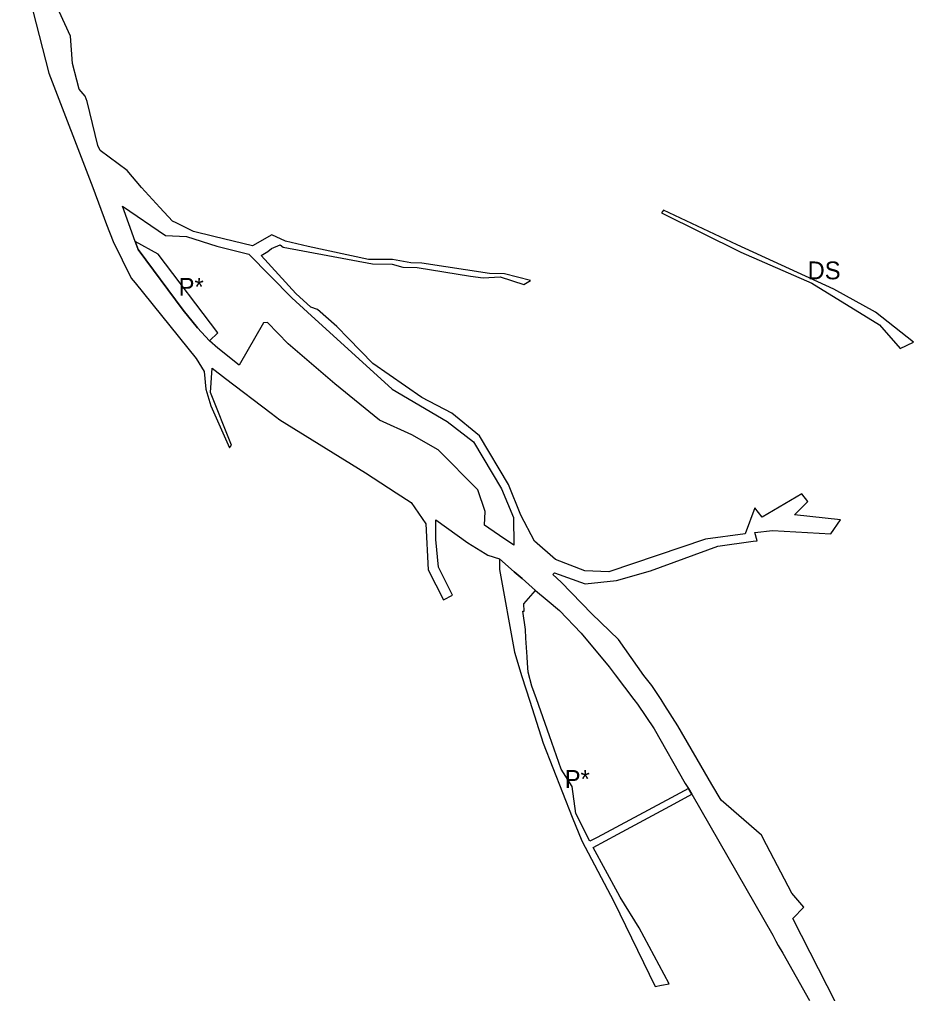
# Model space of a CAD drawing. Extents: x -477304 to -465641, y -1159113 to -1149285.
# Drawn here: x -474865.2 to -474412.9, y -1155046.4 to -1154553.8 of the extents above; entities that cross this region are included whole.
import ezdxf

# ---------------------------------------------------------------- set-up
doc = ezdxf.new("R2010")
doc.units = 0
doc.layers.add('34', color=7, linetype='Continuous')
doc.layers.add('35', color=7, linetype='Continuous')

msp = doc.modelspace()

# ---------------------------------------------------------------- linework, layer by layer
at = {"layer": '34'}
for p, q in [((-474806.65, -1154666.07), (-474805.24, -1154670.15)), ((-474795.11, -1154672.55), (-474806.65, -1154666.07)), ((-474805.24, -1154670.15), (-474782.43, -1154700.72)), ((-474764.82, -1154712.21), (-474795.11, -1154672.55)), ((-474769.12, -1154716.23), (-474764.82, -1154712.21)), ((-474614.91, -1154833.09), (-474622.36, -1154826.48)), ((-474622.36, -1154826.48), (-474622.33, -1154831.94)), ((-474610.93, -1154836.56), (-474614.91, -1154833.09)), ((-474604.08, -1154842.58), (-474610.93, -1154836.56)), ((-474610.12, -1154849.34), (-474604.08, -1154842.58)), ((-474609.89, -1154852.95), (-474610.12, -1154849.34)), ((-474609.01, -1154866.68), (-474609.29, -1154862.3)), ((-474608.41, -1154876.12), (-474609.01, -1154866.68)), ((-474608.21, -1154879.35), (-474608.41, -1154876.12)), ((-474603.72, -1154897.29), (-474605.96, -1154890.99)), ((-474607.04, -1154898.47), (-474600.23, -1154919.72)), ((-474597.09, -1154916.02), (-474603.72, -1154897.29)), ((-474526.67, -1154942.72), (-474535.48, -1154947.42)), ((-474525.04, -1154945.58), (-474526.67, -1154942.72)), ((-474535.48, -1154947.42), (-474572.91, -1154967.39)), ((-474533.92, -1154950.37), (-474525.04, -1154945.58)), ((-474562.54, -1154965.79), (-474533.92, -1154950.37)), ((-474574.98, -1154972.58), (-474562.54, -1154965.79)), ((-474562.48, -1154995.51), (-474574.98, -1154972.58)), ((-474536.56, -1155041.38), (-474551.7, -1155013.07)), ((-474540.39, -1155042.17), (-474536.56, -1155041.38)), ((-474543.58, -1155042.83), (-474540.39, -1155042.17))]:
    msp.add_line(p, q, dxfattribs=at)
for points in [[(-474782.43, -1154700.72), (-474775.12, -1154709.75), (-474769.12, -1154716.23)], [(-474622.33, -1154831.94), (-474614.8, -1154873.75), (-474611.04, -1154885.99), (-474607.04, -1154898.47)], [(-474609.29, -1154862.3), (-474610.56, -1154853.04), (-474609.89, -1154852.95)], [(-474605.96, -1154890.99), (-474607.92, -1154883.93), (-474608.21, -1154879.35)], [(-474585.68, -1154941.61), (-474591.13, -1154932.86), (-474597.09, -1154916.02)], [(-474600.23, -1154919.72), (-474585.53, -1154957.25), (-474580.79, -1154969.17), (-474564.55, -1154999.77), (-474543.58, -1155042.83)], [(-474572.91, -1154967.39), (-474576.61, -1154969.37), (-474583.78, -1154955.28), (-474585.68, -1154941.61)], [(-474551.7, -1155013.07), (-474561.35, -1154997.58), (-474562.48, -1154995.51)]]:
    msp.add_lwpolyline(points, dxfattribs=at)
at = {"layer": '35'}
for p, q in [((-474838.31, -1154576.14), (-474839.4, -1154562.29)), ((-474830.9, -1154595.31), (-474831.91, -1154592.5)), ((-474825.49, -1154617.48), (-474830.9, -1154595.31)), ((-474824.38, -1154620.12), (-474825.49, -1154617.48)), ((-474828.11, -1154638.77), (-474821.13, -1154657.4)), ((-474806.65, -1154666.07), (-474813.12, -1154648.24)), ((-474539.37, -1154650.22), (-474540.4, -1154651.54)), ((-474540.4, -1154651.54), (-474500.33, -1154671.41)), ((-474502.17, -1154667.8), (-474539.37, -1154650.22)), ((-474821.13, -1154657.4), (-474817.79, -1154666.07)), ((-474766.83, -1154663.63), (-474777.22, -1154661)), ((-474817.79, -1154666.07), (-474808.7, -1154684.7)), ((-474805.24, -1154670.15), (-474806.65, -1154666.07)), ((-474780.67, -1154663.48), (-474765.36, -1154668.5)), ((-474747.33, -1154668.2), (-474766.83, -1154663.63)), ((-474737.54, -1154662.69), (-474747.33, -1154668.2)), ((-474730.7, -1154665.87), (-474737.54, -1154662.69)), ((-474719.22, -1154668.63), (-474730.7, -1154665.87)), ((-474782.43, -1154700.72), (-474805.24, -1154670.15)), ((-474765.36, -1154668.5), (-474749.12, -1154672.51)), ((-474742.86, -1154673.12), (-474739.51, -1154671.12)), ((-474739.51, -1154671.12), (-474737.77, -1154669.58)), ((-474737.77, -1154669.58), (-474733.39, -1154667.74)), ((-474688.61, -1154675.12), (-474719.22, -1154668.63)), ((-474453.2, -1154690.19), (-474502.17, -1154667.8)), ((-474725.32, -1154692.43), (-474742.86, -1154673.12)), ((-474686.55, -1154677.31), (-474676.66, -1154677.47)), ((-474637.1, -1154683.56), (-474630.7, -1154684.37)), ((-474606.68, -1154685.72), (-474619.79, -1154682.46)), ((-474432.2, -1154701.74), (-474453.2, -1154690.19)), ((-474717.74, -1154699.23), (-474725.32, -1154692.43)), ((-474714.51, -1154700.52), (-474717.74, -1154699.23)), ((-474704.63, -1154709.05), (-474714.51, -1154700.52)), ((-474412.91, -1154716.9), (-474432.2, -1154701.74)), ((-474741.77, -1154707.22), (-474754.02, -1154728.61)), ((-474698.74, -1154715.1), (-474704.63, -1154709.05)), ((-474430.19, -1154708.17), (-474419.75, -1154720.15)), ((-474764.84, -1154720.04), (-474769.12, -1154716.23)), ((-474686.45, -1154727.73), (-474698.74, -1154715.1)), ((-474754.02, -1154728.61), (-474764.84, -1154720.04)), ((-474419.75, -1154720.15), (-474412.91, -1154716.9)), ((-474775.85, -1154725.16), (-474771.78, -1154731.76)), ((-474771.78, -1154731.76), (-474770.92, -1154740.75)), ((-474760.97, -1154735.34), (-474737.91, -1154752.94)), ((-474770.92, -1154740.75), (-474768.34, -1154749.1)), ((-474683.1, -1154756.46), (-474705.7, -1154737.98)), ((-474676.74, -1154740.67), (-474648.86, -1154757.1)), ((-474757.91, -1154769.11), (-474768.65, -1154742.5)), ((-474768.34, -1154749.1), (-474758.93, -1154770.42)), ((-474737.91, -1154752.94), (-474733.42, -1154756.31)), ((-474733.42, -1154756.31), (-474690.2, -1154782.99)), ((-474758.93, -1154770.42), (-474757.91, -1154769.11)), ((-474690.2, -1154782.99), (-474674.6, -1154793.18)), ((-474611.64, -1154804.51), (-474617.78, -1154788.89)), ((-474674.6, -1154793.18), (-474667.1, -1154798.07)), ((-474469.46, -1154793.7), (-474489.41, -1154805.56)), ((-474667.1, -1154798.07), (-474659.66, -1154808.84)), ((-474630.02, -1154809.47), (-474629.6, -1154802.57)), ((-474493.15, -1154800.71), (-474498.13, -1154813.93)), ((-474489.41, -1154805.56), (-474493.15, -1154800.71)), ((-474654.55, -1154816.84), (-474654.64, -1154806.78)), ((-474654.64, -1154806.78), (-474638.39, -1154818.44)), ((-474627.68, -1154811.08), (-474630.02, -1154809.47)), ((-474622.42, -1154814.7), (-474627.68, -1154811.08)), ((-474615.12, -1154819.71), (-474622.42, -1154814.7)), ((-474498.13, -1154813.93), (-474518.19, -1154816.58)), ((-474492.08, -1154817.4), (-474493.19, -1154813.28)), ((-474638.39, -1154818.44), (-474629.56, -1154823.93)), ((-474518.19, -1154816.58), (-474567.08, -1154833.17)), ((-474493.97, -1154817.66), (-474492.08, -1154817.4)), ((-474629.56, -1154823.93), (-474628.31, -1154824.71)), ((-474628.31, -1154824.71), (-474622.36, -1154826.48)), ((-474622.36, -1154826.48), (-474614.91, -1154833.09)), ((-474579.2, -1154832.67), (-474594.07, -1154826.96)), ((-474614.91, -1154833.09), (-474610.93, -1154836.56)), ((-474595.46, -1154834.53), (-474594.59, -1154833.69)), ((-474591.24, -1154838.38), (-474595.46, -1154834.53)), ((-474594.59, -1154833.69), (-474579.09, -1154839.11)), ((-474567.08, -1154833.17), (-474579.2, -1154832.67)), ((-474610.93, -1154836.56), (-474604.08, -1154842.58)), ((-474579.09, -1154839.11), (-474563.17, -1154837.58)), ((-474604.08, -1154842.58), (-474598.31, -1154847.51)), ((-474650.7, -1154847.35), (-474646.16, -1154844.95)), ((-474598.31, -1154847.51), (-474592.06, -1154852.66)), ((-474592.06, -1154852.66), (-474580.98, -1154864.09)), ((-474580.98, -1154864.09), (-474566.93, -1154881.17)), ((-474549.35, -1154885.54), (-474562.1, -1154867.34)), ((-474566.93, -1154881.17), (-474563.85, -1154885.24)), ((-474563.85, -1154885.24), (-474554.46, -1154897.67)), ((-474545.33, -1154890.58), (-474549.35, -1154885.54)), ((-474540.66, -1154897.76), (-474545.33, -1154890.58)), ((-474554.46, -1154897.67), (-474552.62, -1154900.1)), ((-474538.77, -1154900.7), (-474540.66, -1154897.76)), ((-474552.62, -1154900.1), (-474544.14, -1154912.49)), ((-474532.08, -1154910.96), (-474538.77, -1154900.7)), ((-474544.14, -1154912.49), (-474528.39, -1154940.1)), ((-474520.43, -1154931.09), (-474532.08, -1154910.96)), ((-474528.39, -1154940.1), (-474526.67, -1154942.72)), ((-474526.67, -1154942.72), (-474525.04, -1154945.58)), ((-474525.04, -1154945.58), (-474484.11, -1155016.91)), ((-474468.38, -1155002.64), (-474474.4, -1154995.69)), ((-474473.97, -1155008.34), (-474468.38, -1155002.64)), ((-474452.27, -1155051.03), (-474473.97, -1155008.34)), ((-474481.35, -1155022.01), (-474479.1, -1155025.98)), ((-474479.1, -1155025.98), (-474465.55, -1155049.89))]:
    msp.add_line(p, q, dxfattribs=at)
for points in [[(-474839.4, -1154562.29), (-474860.32, -1154516.54), (-474865.21, -1154505.85)], [(-474861.66, -1154536.87), (-474850.4, -1154581), (-474828.11, -1154638.77)], [(-474831.91, -1154592.5), (-474835.09, -1154589.12), (-474836.26, -1154584.42), (-474838.31, -1154576.14)], [(-474803.42, -1154638.79), (-474810.76, -1154630.1), (-474824.38, -1154620.12)], [(-474787.72, -1154655.82), (-474794.2, -1154648.81), (-474803.42, -1154638.79)], [(-474813.12, -1154648.24), (-474791.27, -1154663.04), (-474780.67, -1154663.48)], [(-474777.22, -1154661), (-474785.96, -1154656.7), (-474787.72, -1154655.82)], [(-474733.39, -1154667.74), (-474731.79, -1154668.98), (-474686.55, -1154677.31)], [(-474500.33, -1154671.41), (-474464.4, -1154687.15), (-474430.19, -1154708.17)], [(-474749.12, -1154672.51), (-474727.38, -1154694.54), (-474719.43, -1154701.78), (-474676.74, -1154740.67)], [(-474667.26, -1154676.92), (-474676.53, -1154675.18), (-474688.61, -1154675.12)], [(-474619.79, -1154682.46), (-474627.35, -1154682.18), (-474661.62, -1154676.95), (-474667.26, -1154676.92)], [(-474676.66, -1154677.47), (-474671.34, -1154679.05), (-474664.06, -1154679.24), (-474637.1, -1154683.56)], [(-474808.7, -1154684.7), (-474806.72, -1154686.99), (-474775.85, -1154725.16)], [(-474630.7, -1154684.37), (-474622.11, -1154683.87), (-474610.01, -1154687.78), (-474606.68, -1154685.72)], [(-474769.12, -1154716.23), (-474775.12, -1154709.75), (-474782.43, -1154700.72)], [(-474705.7, -1154737.98), (-474729.35, -1154717.77), (-474739.73, -1154706.96), (-474741.77, -1154707.22)], [(-474768.65, -1154742.5), (-474767.81, -1154730.12), (-474760.97, -1154735.34)], [(-474646.53, -1154752.94), (-474661.68, -1154744.91), (-474686.45, -1154727.73)], [(-474617.78, -1154788.89), (-474632.51, -1154764.4), (-474646.53, -1154752.94)], [(-474629.6, -1154802.57), (-474633.41, -1154791.71), (-474653.35, -1154771.35), (-474666.71, -1154763.83), (-474683.1, -1154756.46)], [(-474648.86, -1154757.1), (-474635.59, -1154767.38), (-474621.32, -1154791.18), (-474615.33, -1154805.69), (-474615.12, -1154819.71)], [(-474473.19, -1154804.35), (-474466.41, -1154797.55), (-474469.46, -1154793.7)], [(-474594.07, -1154826.96), (-474604.67, -1154817.65), (-474611.64, -1154804.51)], [(-474454.76, -1154813.98), (-474449.84, -1154806.84), (-474473.19, -1154804.35)], [(-474659.66, -1154808.84), (-474658.42, -1154832.14), (-474650.7, -1154847.35)], [(-474493.19, -1154813.28), (-474484.24, -1154812.22), (-474454.76, -1154813.98)], [(-474646.16, -1154844.95), (-474653.25, -1154830.73), (-474654.55, -1154816.84)], [(-474563.17, -1154837.58), (-474545.95, -1154832.68), (-474511.93, -1154820.1), (-474493.97, -1154817.66)], [(-474562.1, -1154867.34), (-474575.64, -1154854.29), (-474591.24, -1154838.38)], [(-474510.24, -1154948.53), (-474514.88, -1154940.67), (-474520.43, -1154931.09)], [(-474474.4, -1154995.69), (-474487.36, -1154971.11), (-474489.87, -1154966.34), (-474510.24, -1154948.53)], [(-474484.11, -1155016.91), (-474482.5, -1155019.97), (-474481.35, -1155022.01)]]:
    msp.add_lwpolyline(points, dxfattribs=at)

# ---------------------------------------------------------------- texts
at = {"layer": '34'}
for p in [(-474784.7, -1154693.5), (-474589.39, -1154942.38)]:
    msp.add_text('P*', height=9, dxfattribs=at).set_placement(p)
at = {"layer": '35'}
msp.add_text('DS', height=9, dxfattribs=at).set_placement((-474466.52, -1154685.19))

doc.saveas('drawing.dxf')
